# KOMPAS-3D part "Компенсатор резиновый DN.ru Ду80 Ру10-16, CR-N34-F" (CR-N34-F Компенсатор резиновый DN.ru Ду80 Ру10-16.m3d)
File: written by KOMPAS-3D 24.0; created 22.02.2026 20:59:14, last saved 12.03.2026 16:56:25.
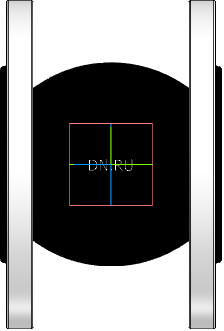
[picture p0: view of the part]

Document properties: Автор: DN.RU; Полное имя файла: CR-N34-F Компенсатор резиновый DN.ru Ду80 Ру10-16.cdw

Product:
- Body: Твердое тело2  | qty 1
    Масса: 10.337867
- Part/product: Компенсатор резиновый DN.ru Ду80 Ру10-16  | designation CR-N34-F
    Масса: 7.5
    Раздел спецификации: Прочие изделия
    Форматы листов документа: A2
    Комментарий: D140-02091
    Примечание: D140-02091
    additional columns: Типовые

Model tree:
1. Твердое тело2  (labels: Твердое тело2)

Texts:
  CR-N34-F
